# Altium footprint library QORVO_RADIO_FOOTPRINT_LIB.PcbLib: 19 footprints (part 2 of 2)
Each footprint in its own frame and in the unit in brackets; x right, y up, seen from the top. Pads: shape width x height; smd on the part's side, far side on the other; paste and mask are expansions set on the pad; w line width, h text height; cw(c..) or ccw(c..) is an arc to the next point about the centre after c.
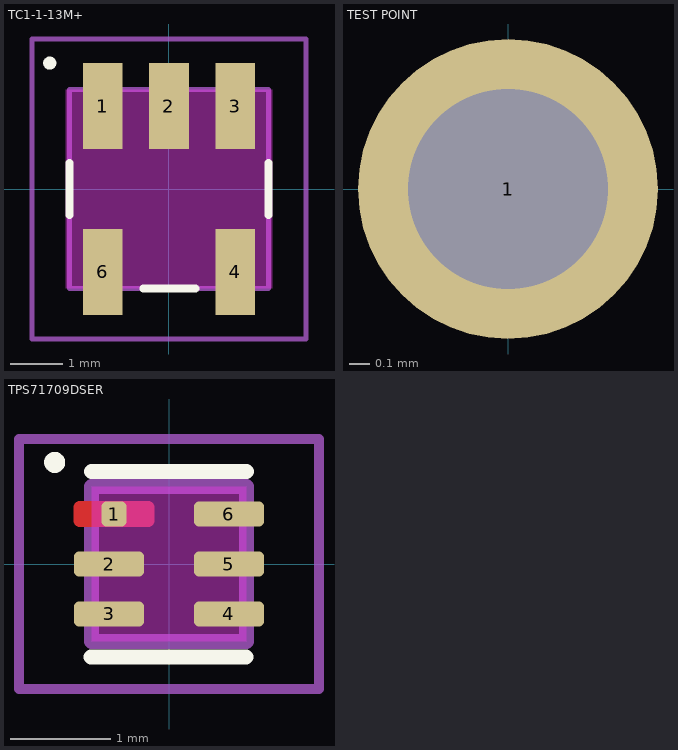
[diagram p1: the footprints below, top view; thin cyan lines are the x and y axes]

## TC1-1-13M+ [mm] "1:1 BALUN,"
pads (5):
  rect 0.76x1.65 smd: 1(-1.27,1.59) 2(0,1.59) 3(1.27,1.59) 4(1.27,-1.59) 6(-1.27,-1.59)
Top Overlay:
  circle w0.15: c-2.286,2.413 r0.05
  lines w0.15: -1.905,-0.5 -1.905,0.5 ; -0.492,-1.905 0.508,-1.905 ; 1.905,-0.5 1.905,0.5
Keep-Out Layer:
  rectangle: -1.98,-1.905 1.98,1.905
Mechanical 1:
  lines w0.1: -1.905,-1.905 1.905,-1.905 1.905,1.905 -1.905,1.905 -1.905,-1.905
Mechanical 15:
  lines w0.1: -2.625,-2.875 2.625,-2.875 2.625,2.875 -2.625,2.875 -2.625,-2.875
3D body "TC1-1-13M+.stp": height 4.06, standoff 0, extent -1.905,-1.905 1.905,1.905

## TEST POINT [mm] "TEST POINT"
pads (1):
  round 1.5 hole 1: 1(0,0)

## TPS71709DSER [mm] "0.9V REG (DSE)"
pads (6):
  rrect40% 0.25x0.25 smd mask+0.05: 1(-0.55,0.5)
  rrect40% 0.7x0.25 smd mask+0.05: 2(-0.6,0) 3(-0.6,-0.5) 4(0.6,-0.5) 5(0.6,0) 6(0.6,0.5)
Top Layer:
  region: -0.9,0.375 -0.91,0.375 -0.928,0.383 -0.942,0.397 -0.95,0.415 -0.95,0.425 -0.95,0.575 -0.95,0.585 -0.942,0.603 -0.928,0.617 -0.91,0.625 -0.9,0.625 -0.2,0.625 -0.19,0.625 -0.172,0.617 -0.158,0.603 -0.15,0.585 -0.15,0.575 -0.15,0.425 -0.15,0.415 -0.158,0.397 -0.172,0.383 -0.19,0.375 -0.2,0.375
Top Overlay:
  circle w0.15: c-1.143,1.016 r0.03
  lines w0.15: -0.78,-0.93 0.77,-0.93 ; -0.777,0.925 0.773,0.925
Keep-Out Layer:
  rectangle: -0.775,-0.775 0.775,0.775
Mechanical 13:
  lines w0.15: -0.775,-0.775 0.775,-0.775 0.775,0.775 -0.775,0.775 -0.775,-0.775
Mechanical 15:
  lines w0.1: -1.5,-1.25 1.5,-1.25 1.5,1.25 -1.5,1.25 -1.5,-1.25
3D body "DSE0006A.stp": height 0.8, standoff 0, extent -0.75,-0.75 0.75,0.75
